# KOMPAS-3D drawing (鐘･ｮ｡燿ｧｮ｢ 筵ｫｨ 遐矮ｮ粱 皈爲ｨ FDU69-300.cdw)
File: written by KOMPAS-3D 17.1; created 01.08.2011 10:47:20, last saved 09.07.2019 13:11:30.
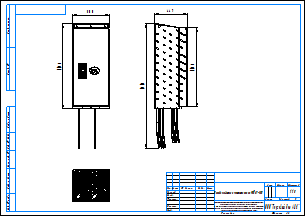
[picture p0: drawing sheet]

Title block, sheet 1: name: Преобразователи частоты серии FDU69-300; scale: 1:10; sheets: 1; sheet format: A3; stored path: \\adlc.lan\data\АДЛ_ПКД\3D-модели\Поставщики\Оборудование Emotron\Преобразователи частоты\Серия FDU 2.0\KOMPAS 2D\Преобразователи частоты серии FDU69-300.cdw

Views: Спереди 1
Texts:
  Рама для чертежей
  Лит-Масса-Масштаб
  Материал-Предприятие
  Масштаб
  Изм.
  Лист
  № докум.
  Подп.
  Дата
  Лит.
  Разраб.
  Пров.
  Т.контр.
  Листов
  Внимание! Данный продукт является объектом авторского права ООО «Торговый Дом АДЛ».
  Запрещается изменение, копирование, распространение
  (в том числе путем копирования на другие сайты и ресурсы в Интернете)
  или любое иное использование информации и объектов без предварительного
  согласия правообладателя (ООО «Торговый Дом АДЛ»).
  Н.контр.
  Утв.
  ООО "Торговый дом АДЛ"
  Изменение
  Номер документа
  Подпись
  Обозначение документа
  Наименование изделия
  Масса изделия по ГОСТ 2.109-73
  Порядковый номер листа
  Общее количество листов в документе
  Характер работы, выполненной лицом, подписавшим документ
  Наименование или индекс предприятия, выпускающего документ
  Инв. № подл.
  Подп. и дата
  Взам. инв. №
  Инв. № дубл.
  Инвентарный номер подлинника по ГОСТ 2.501-68
  Подпись принявшего подлинник в отдел технической документации
  Инвентарный номер подлинника, взамен которого выпущен данный подлинник
  Инвентарный номер дубликата по ГОСТ 2.502-68
  Подпись принявшего дубликат в отдел технической документации
  Справ. №
  Перв. примен.
  Обозначение документа, взамен или на основании которого выпущен данный документ
  Обозначение документа, в котором впервые записан данный документ
  Подпись лица, копировавшего чертеж
  Обозначение формата листа
  !Рама для чертежа
Dimensions and other numbers on the sheet: 1176; 500; 1718; 1100; 449; 1:10; 1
